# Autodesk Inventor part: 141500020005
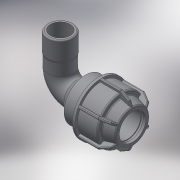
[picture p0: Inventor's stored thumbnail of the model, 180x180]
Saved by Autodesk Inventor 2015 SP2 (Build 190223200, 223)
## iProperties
Created: 2017-08
Part Number: 141500020005
Material: Generic
Description: L.14 90° ELBOW FEMALE ADAPTOR (SILVER) 20-1/2"
Document SubType Name: Modeling
Designer: KIM
Density: 1 g/cm^3
Appearance: Default
Author: KIM
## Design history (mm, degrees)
derived "141500.ipt"
feature "Solid1::141500.ipt"
feature "Solid2::141500.ipt"
tag "TaggingFeature1"
body "Solid1"
body "Solid2"
other parameters: "d2" = 44, "d4" = 15 deg, "d5" = 29.04, "d6" = 9.5832, "d10" = 42, "d16" = 20.4, "d17" = 2.2, "d22" = 32, "d24" = 2.2, "d25" = 37.8, "d26" = 31.5, "d27" = 2.2, "d28" = 135 deg, "d29" = 1.32, "d31" = 1, "d46" = 150 deg, "d49" = 2.1, "d50" = 0, "d58" = 0.6, "d61" = 360 deg, "d63" = 18, "d94" = 42, "d95" = 18.631, "d96" = 24.2203, "d97" = 17, "d98" = 14.9048, "d99" = 21.79827, "d100" = 135 deg, "d108" = 1, "d112" = 22.1, "d113" = 56, "d114" = 44.88, "d115" = 21.79827, "d116" = 45 deg, "d117" = 0, "d118" = 0, "G_" = 18.631, "E_" = 42, "A_" = 56, "l_" = 44, "l_2" = 17, "A_1" = 42
